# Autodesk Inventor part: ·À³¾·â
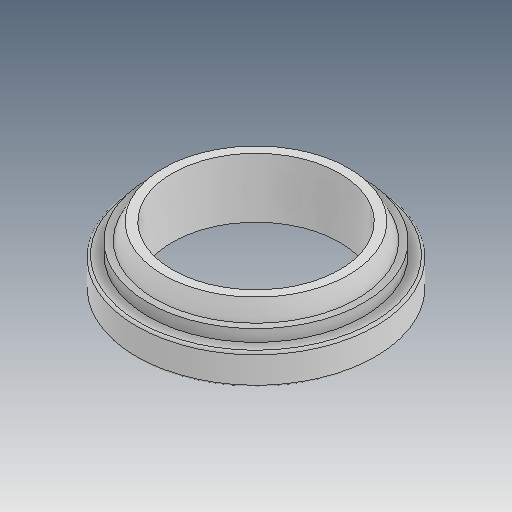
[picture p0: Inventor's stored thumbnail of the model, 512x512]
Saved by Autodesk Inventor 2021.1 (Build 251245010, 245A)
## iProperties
Created: 2015-08
Part Number: ·À³¾·â
Material: Ogólny
Document SubType Name: Modeling
Designer: user
Density: 1 g/cm^3
Appearance: Domyślna
Author: user
Revision Number: ÈÎºÎ
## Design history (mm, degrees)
feature "Ðý×ª1"
node "Bryła1"
